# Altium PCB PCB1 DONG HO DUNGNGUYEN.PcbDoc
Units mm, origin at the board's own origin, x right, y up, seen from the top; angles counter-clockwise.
Board outline 54.94 x 47.62 mm, 2 copper layers (Top Layer, Bottom Layer); 32 components, 16 nets, 156 pads, 0 vias.
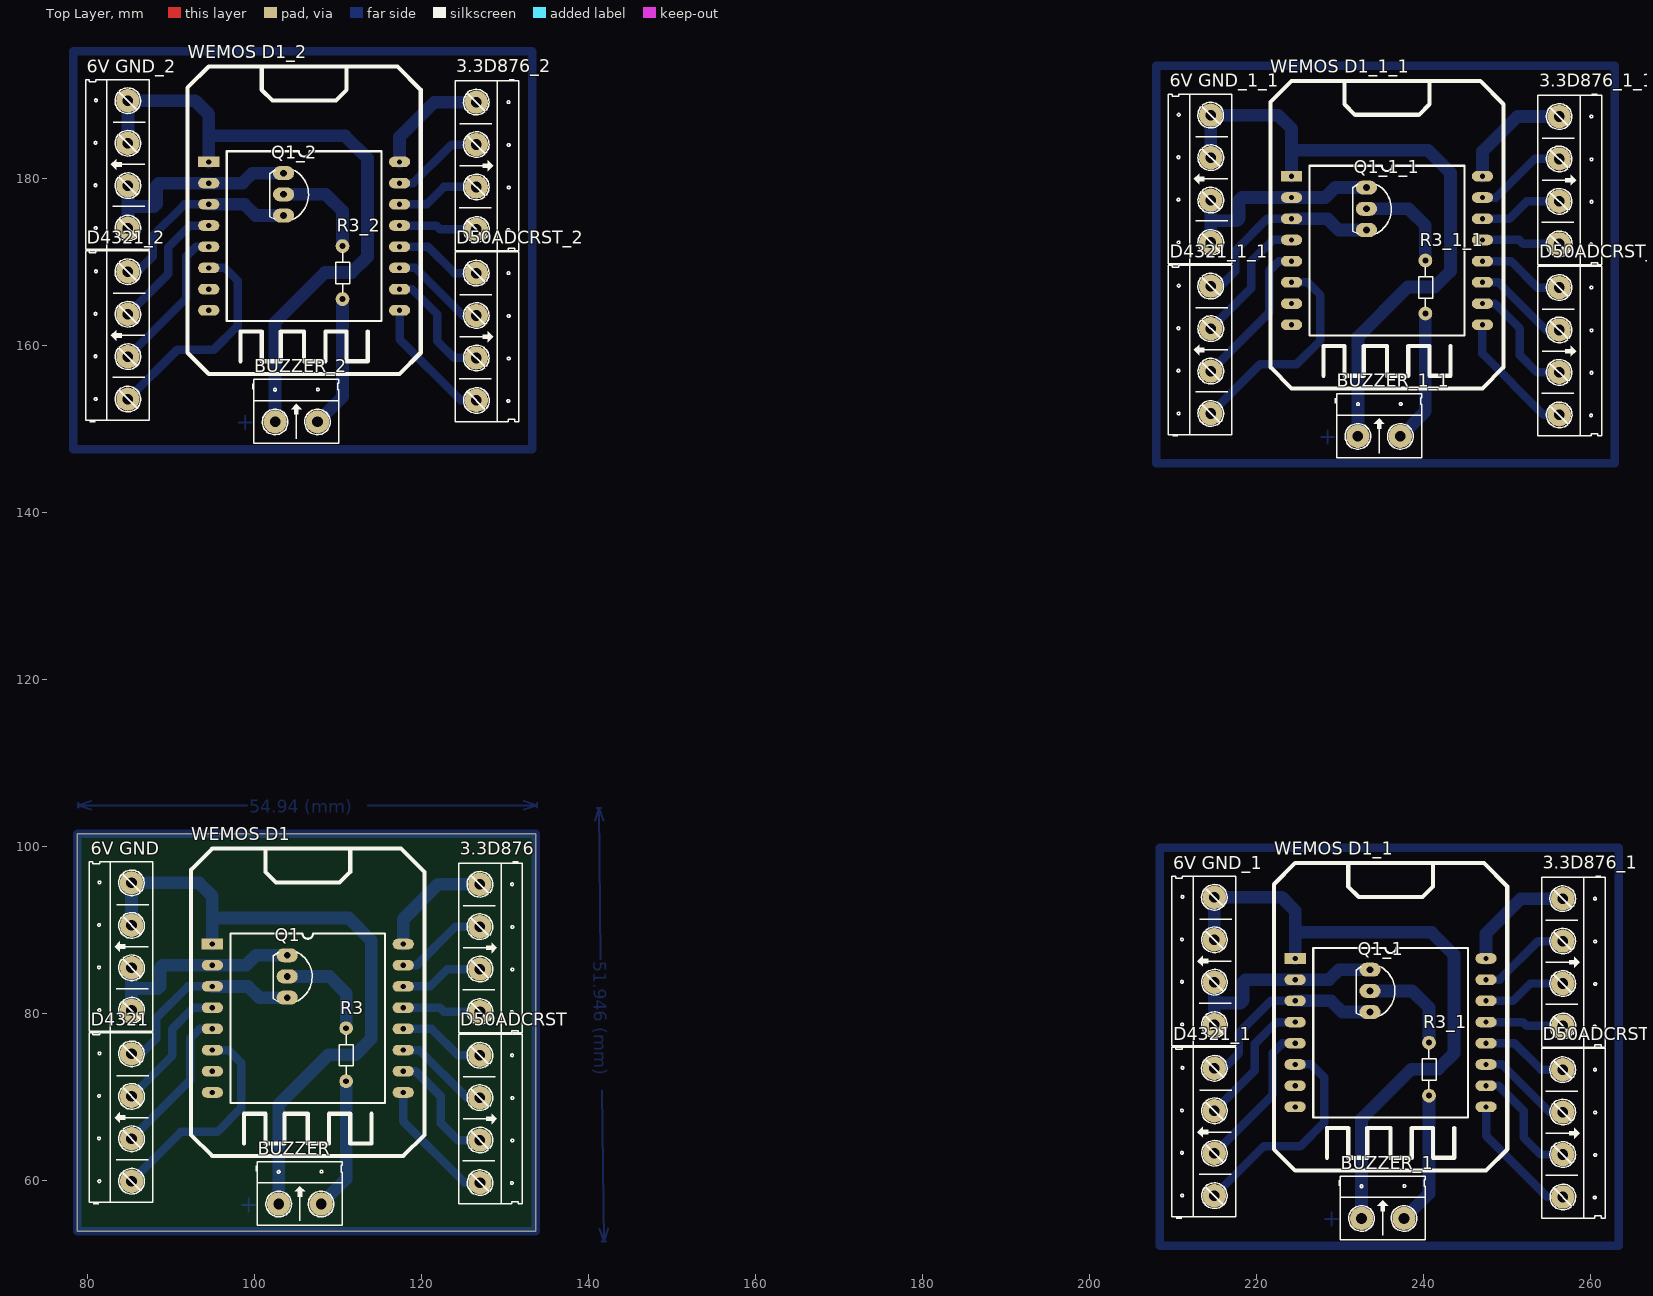
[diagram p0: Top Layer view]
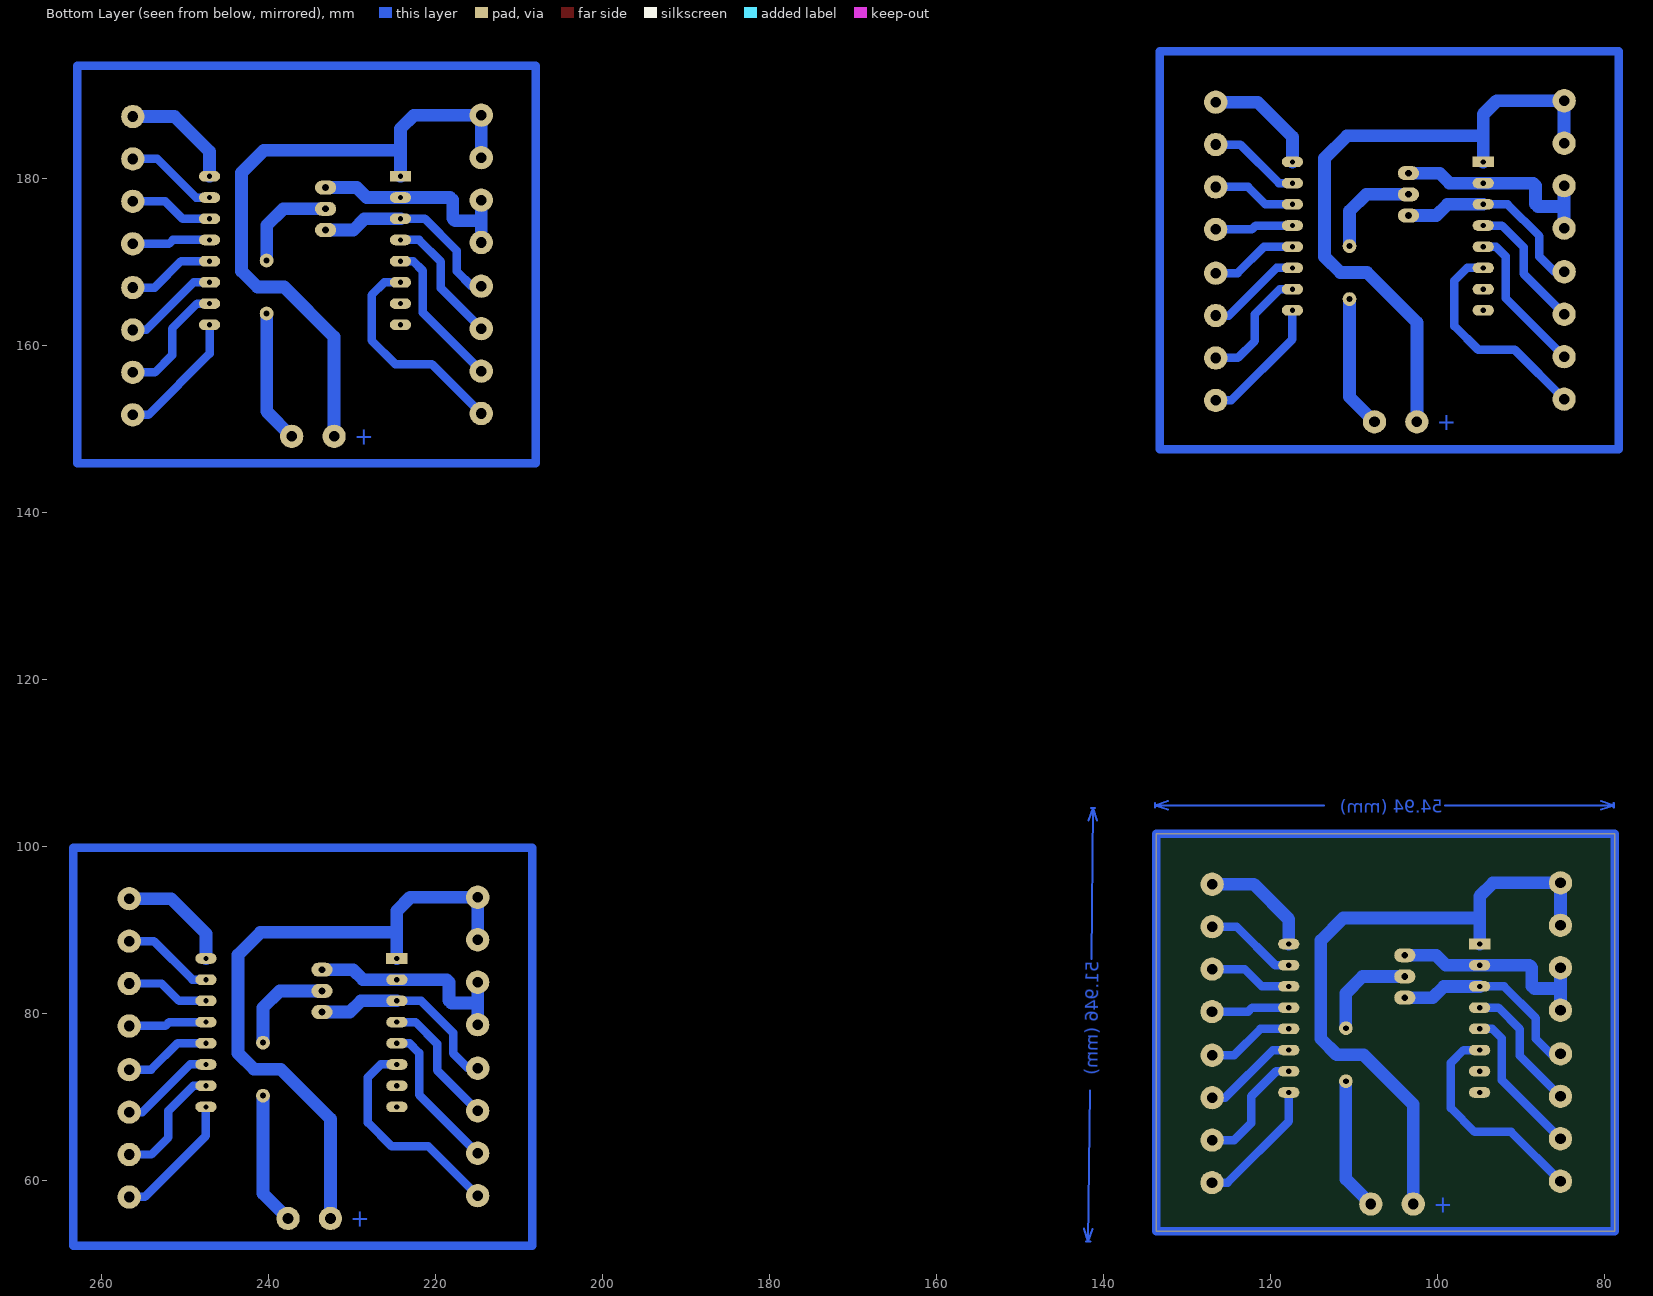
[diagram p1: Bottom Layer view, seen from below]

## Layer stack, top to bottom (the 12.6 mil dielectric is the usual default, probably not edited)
Top Solder: solder mask 0.0102, Solder Resist, Dk 3.5
Top Layer: signal copper 0.0356
Dielectric 1: dielectric 0.32, FR-4, Dk 4.8
Bottom Layer: signal copper 0.0356
Bottom Solder: solder mask 0.0102, Solder Resist, Dk 3.5

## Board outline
78.689,53.975 78.689,101.6 133.629,101.6 133.629,53.975

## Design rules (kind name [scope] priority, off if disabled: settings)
Clearance [All] p1: gap=0.254 ignorepadtopadclearanceinfootprint=FALSE except(0: Arc-Hole Track-Hole SMDPad-Hole THPad-Hole Via-Hole Fill-Hole Poly-Hole Region-Hole Text-Hole)
PolygonConnect [All] p1: connectstyle=Relief reliefconductorwidth=0.254 reliefentries=4 polygonreliefangle="90 Angle" airgapwidth=0.254
RoutingVias [All] p1: holewidth=0.711 width=1.27 viastyle="Through Hole" minholewidth=0.711 minwidth=1.27 maxholewidth=2.54 maxwidth=2.54
SolderMaskExpansion [All] p1: expansion=0.102
Width [All] p1: maxlimit=2.032 minlimit=1.016 preferedwidth=1.524
30 further rules are at their usual default settings.

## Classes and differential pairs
component class DONG_HO: 3.3D876 "6V GND" BUZZER D50ADCRST D4321 HD? Q1 R3 "WEMOS D1"

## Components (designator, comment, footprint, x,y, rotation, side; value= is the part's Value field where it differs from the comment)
3.3D876 "Header 4" HED4 126.939,95.528 r270 top
3.3D876_1 "Header 4" HED4 256.632,93.801 r270 top (schematic designator 3.3D876)
3.3D876_1_1 "Header 4" HED4 256.2,187.476 r270 top (schematic designator 3.3D876)
3.3D876_2 "Header 4" HED4 126.507,189.203 r270 top (schematic designator 3.3D876)
"6V GND" "Header 4" HED4 85.219,80.44 r90 top
"6V GND_1" "Header 4" HED4 214.911,78.713 r90 top (schematic designator "6V GND")
"6V GND_1_1" "Header 4" HED4 214.479,172.388 r90 top (schematic designator "6V GND")
"6V GND_2" "Header 4" HED4 84.787,174.115 r90 top (schematic designator "6V GND")
BUZZER "Header 2" HED2 102.845,57.226 r0 top
BUZZER_1 "Header 2" HED2 232.537,55.499 r0 top (schematic designator BUZZER)
BUZZER_1_1 "Header 2" HED2 232.105,149.174 r0 top (schematic designator BUZZER)
BUZZER_2 "Header 2" HED2 102.413,150.901 r0 top (schematic designator BUZZER)
D50ADCRST "Header 4" HED4 126.939,75.047 r270 top
D50ADCRST_1 "Header 4" HED4 256.632,73.32 r270 top (schematic designator D50ADCRST)
D50ADCRST_1_1 "Header 4" HED4 256.2,166.995 r270 top (schematic designator D50ADCRST)
D50ADCRST_2 "Header 4" HED4 126.507,168.722 r270 top (schematic designator D50ADCRST)
D4321 "Header 4" HED4 85.219,59.959 r90 top
D4321_1 "Header 4" HED4 214.911,58.232 r90 top (schematic designator D4321)
D4321_1_1 "Header 4" HED4 214.479,151.907 r90 top (schematic designator D4321)
D4321_2 "Header 4" HED4 84.787,153.635 r90 top (schematic designator D4321)
Q1 "C1815" QTO-92 103.861,84.48 r270 top
Q1_1 "C1815" QTO-92 233.553,82.753 r270 top (schematic designator Q1)
Q1_1_1 "C1815" QTO-92 233.121,176.428 r270 top (schematic designator Q1)
Q1_2 "C1815" QTO-92 103.429,178.156 r270 top (schematic designator Q1)
R3 "100" RES-1/8W-SMALL 110.922,75.108 r270 top
R3_1 "100" RES-1/8W-SMALL 240.614,73.381 r270 top (schematic designator R3)
R3_1_1 "100" RES-1/8W-SMALL 240.182,167.056 r270 top (schematic designator R3)
R3_2 "100" RES-1/8W-SMALL 110.49,168.783 r270 top (schematic designator R3)
"WEMOS D1" "Component_1" "ESP WEMOS MINI" 94.894,88.367 r0 top
"WEMOS D1_1" "Component_1" "ESP WEMOS MINI" 224.587,86.639 r0 top (schematic designator "WEMOS D1")
"WEMOS D1_1_1" "Component_1" "ESP WEMOS MINI" 224.155,180.315 r0 top (schematic designator "WEMOS D1")
"WEMOS D1_2" "Component_1" "ESP WEMOS MINI" 94.463,182.042 r0 top (schematic designator "WEMOS D1")

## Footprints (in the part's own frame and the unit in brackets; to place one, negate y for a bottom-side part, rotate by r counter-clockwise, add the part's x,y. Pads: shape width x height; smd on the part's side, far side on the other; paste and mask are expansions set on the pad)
"ESP WEMOS MINI" [mm]
  rect 2.54x1.27 hole 0.635: 1(0,0)
  oval 2.54x1.27 hole 0.635: 2(0,-2.54) 3(0,-5.08) 4(0,-7.62) 5(0,-10.16) 6(0,-12.7) 7(0,-15.24) 8(0,-17.78) 9(22.86,-17.78) 10(22.86,-15.24) 11(22.86,-12.7) 12(22.86,-10.16) 13(22.86,-7.62) 14(22.86,-5.08) 15(22.86,-2.54) 16(22.86,0)
  silkscreen extent -2.54,-25.4 25.4,11.43
HED2 [mil] "Header 2, 2 pin, hight 300mil, Pin to Pin 200, Colour Green"
  round 110 hole 50: 1(0,0) 2(200,0)
  silkscreen extent -106,-100 300,200, body extent -92,-140 302,155, height 394
HED4 [mil] "Header 4, 4 pin, hight 300mil, Pin to Pin 200, Colour Green"
  round 110 hole 50: 1(0,0) 2(200,0) 3(400.06,0.06) 4(600.39,0.39)
  silkscreen extent -106,-100 700,200
QTO-92 [mil] "TO-92"
  oval 66x100 hole 32: 1(-100,0) 2(0,0) 3(100,0)
  silkscreen extent -117,-65 120,118, body extent -109,-66 109,95, height 245
RES-1/8W-SMALL [mil] "R 1/8W, 2 pin, 200mil"
  round 65 hole 28: 1(-125,0) 2(125,0)
  silkscreen extent -95,-32 95,34, body extent -135,-35 135,37, height 76

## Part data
3.3D876 3.3D876_1 3.3D876_1_1 3.3D876_2 "6V GND" "6V GND_1" "6V GND_1_1" "6V GND_2" D50ADCRST D50ADCRST_1 D50ADCRST_1_1 D50ADCRST_2 D4321 D4321_1 D4321_1_1 D4321_2: library part Hed4, "Header 4 (Green)"
BUZZER BUZZER_1 BUZZER_1_1 BUZZER_2: library part Hed2, "Header 2 (Green)"
Q1 Q1_1 Q1_1_1 Q1_2: "NPN 600mW, ECB"
R3 R3_1 R3_1_1 R3_2: library part Res, "Res", Manufacturer="Generic Components"

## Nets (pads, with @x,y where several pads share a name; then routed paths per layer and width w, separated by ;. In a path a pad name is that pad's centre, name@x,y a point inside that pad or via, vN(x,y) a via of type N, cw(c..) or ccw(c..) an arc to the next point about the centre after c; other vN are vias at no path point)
D4: "WEMOS D1.3" D4321.4 Q1.3 | length 24
  Bottom Layer w1.016: D4321.4 86.36,75.209 88.163,77.013 88.163,79.477 91.973,83.287 94.894,83.287
  Bottom Layer w1.524: 94.894,83.287 99.187,83.287 100.533,81.94 Q1.3
GND: "6V GND.1" "6V GND.2" "WEMOS D1.2" Q1.1 | length 26.7
  Bottom Layer w1.524: 85.219,80.44 85.219,83.033 ; 85.219,85.52 85.219,83.033 ; Q1.1 100.127,87.02 98.933,85.827 94.894,85.827 88.951,85.827 88.644,85.52 88.644,83.336 88.341,83.033 85.219,83.033
Net3.3D876_1: 3.3D876.1 "WEMOS D1.16" | length 13.9
  Bottom Layer w1.524: 117.754,88.367 117.754,91.338 121.944,95.528 3.3D876.1
Net3.3D876_2: 3.3D876.2 "WEMOS D1.15" | length 11.1
  Bottom Layer w1.016: 117.754,85.827 119.38,85.827 124.001,90.448 3.3D876.2
Net3.3D876_3: 3.3D876.3 "WEMOS D1.14" | length 10
  Bottom Layer w1.016: 117.754,83.287 120.98,83.287 123.06,85.366 3.3D876.3
Net3.3D876_4: 3.3D876.4 "WEMOS D1.13" | length 9.4
  Bottom Layer w1.016: 117.754,80.747 122.149,80.747 122.617,80.278 3.3D876.4
NetBUZZER_2: BUZZER.2 R3.2 | length 15.9
  Bottom Layer w1.524: BUZZER.2 110.922,60.223 R3.2
NetD50ADCRST_1: "WEMOS D1.12" D50ADCRST.1 | length 10.5
  Bottom Layer w1.016: 117.754,78.207 121.158,78.207 124.318,75.047 D50ADCRST.1
NetD50ADCRST_2: "WEMOS D1.11" D50ADCRST.2 | length 11.5
  Bottom Layer w1.016: 117.754,75.667 119.659,75.667 125.359,69.967 D50ADCRST.2
NetD50ADCRST_3: "WEMOS D1.10" D50ADCRST.3 | length 14.5
  Bottom Layer w1.016: 117.754,73.127 119.253,73.127 122.25,70.129 122.25,66.929 124.294,64.885 D50ADCRST.3
NetD50ADCRST_4: "WEMOS D1.9" D50ADCRST.4 | length 15.7
  Bottom Layer w1.016: 117.754,70.587 117.754,67.132 125.09,59.797 D50ADCRST.4
NetD4321_1: "WEMOS D1.6" D4321.1 | length 26.3
  Bottom Layer w1.016: D4321.1 91.121,65.862 95.504,65.862 98.349,68.707 98.349,74.143 96.825,75.667 94.894,75.667
NetD4321_2: "WEMOS D1.5" D4321.2 | length 18.1
  Bottom Layer w1.016: D4321.2 92.227,72.048 92.227,77.064 93.37,78.207 94.894,78.207
NetD4321_3: "WEMOS D1.4" D4321.3 | length 15.9
  Bottom Layer w1.016: D4321.3 90.068,74.972 90.068,78.156 92.659,80.747 94.894,80.747
NetQ1_2: Q1.2 R3.1 | length 12.1
  Bottom Layer w1.524: Q1.2 108.915,84.48 110.922,82.474 R3.1
VCC: "6V GND.3" "6V GND.4" "WEMOS D1.1" BUZZER.1 | length 79.3
  Bottom Layer w1.524: 85.217,90.602 85.217,95.682 85.209,95.69 93.286,95.69 94.894,94.082 94.894,91.491 ; 94.894,88.367 94.894,91.491 ; BUZZER.1 102.845,69.139 108.814,75.108 112.014,75.108 113.919,77.013 113.919,88.798 111.227,91.491 94.894,91.491
pads on no net: 3.3D876_1.1 3.3D876_1.2 3.3D876_1.3 3.3D876_1.4 3.3D876_1_1.1 3.3D876_1_1.2 3.3D876_1_1.3 3.3D876_1_1.4 3.3D876_2.1 3.3D876_2.2 3.3D876_2.3 3.3D876_2.4 "6V GND_1.1" "6V GND_1.2" "6V GND_1.3" "6V GND_1.4" "6V GND_1_1.1" "6V GND_1_1.2" "6V GND_1_1.3" "6V GND_1_1.4" "6V GND_2.1" "6V GND_2.2" "6V GND_2.3" "6V GND_2.4" "WEMOS D1.7" "WEMOS D1.8" "WEMOS D1_1.1" "WEMOS D1_1.2" "WEMOS D1_1.3" "WEMOS D1_1.4" "WEMOS D1_1.5" "WEMOS D1_1.6" "WEMOS D1_1.7" "WEMOS D1_1.8" "WEMOS D1_1.9" "WEMOS D1_1.10" "WEMOS D1_1.11" "WEMOS D1_1.12" "WEMOS D1_1.13" "WEMOS D1_1.14" "WEMOS D1_1.15" "WEMOS D1_1.16" "WEMOS D1_1_1.1" "WEMOS D1_1_1.2" "WEMOS D1_1_1.3" "WEMOS D1_1_1.4" "WEMOS D1_1_1.5" "WEMOS D1_1_1.6" "WEMOS D1_1_1.7" "WEMOS D1_1_1.8" "WEMOS D1_1_1.9" "WEMOS D1_1_1.10" "WEMOS D1_1_1.11" "WEMOS D1_1_1.12" "WEMOS D1_1_1.13" "WEMOS D1_1_1.14" "WEMOS D1_1_1.15" "WEMOS D1_1_1.16" "WEMOS D1_2.1" "WEMOS D1_2.2" "WEMOS D1_2.3" "WEMOS D1_2.4" "WEMOS D1_2.5" "WEMOS D1_2.6" "WEMOS D1_2.7" "WEMOS D1_2.8" "WEMOS D1_2.9" "WEMOS D1_2.10" "WEMOS D1_2.11" "WEMOS D1_2.12" "WEMOS D1_2.13" "WEMOS D1_2.14" "WEMOS D1_2.15" "WEMOS D1_2.16" BUZZER_1.1 BUZZER_1.2 BUZZER_1_1.1 BUZZER_1_1.2 BUZZER_2.1 BUZZER_2.2 D50ADCRST_1.1 D50ADCRST_1.2 D50ADCRST_1.3 D50ADCRST_1.4 D50ADCRST_1_1.1 D50ADCRST_1_1.2 D50ADCRST_1_1.3 D50ADCRST_1_1.4 D50ADCRST_2.1 D50ADCRST_2.2 D50ADCRST_2.3 D50ADCRST_2.4 D4321_1.1 D4321_1.2 D4321_1.3 D4321_1.4 D4321_1_1.1 D4321_1_1.2 D4321_1_1.3 D4321_1_1.4 D4321_2.1 D4321_2.2 D4321_2.3 D4321_2.4 Q1_1.1 Q1_1.2 Q1_1.3 Q1_1_1.1 Q1_1_1.2 Q1_1_1.3 Q1_2.1 Q1_2.2 Q1_2.3 R3_1.1 R3_1.2 R3_1_1.1 R3_1_1.2 R3_2.1 R3_2.2
copper on no net: | length 1856.8
  Bottom Layer w0.254: 78.831,104.724 78.831,105.232 ; 80.355,104.47 78.831,104.978 ; 80.355,105.486 78.831,104.978 ; 99.039,104.978 78.831,104.978 ; 113.563,104.978 133.771,104.978 ; 132.247,104.47 133.771,104.978 ; 132.247,105.486 133.771,104.978 ; 133.771,104.724 133.771,105.232 ; 140.708,103.144 141.199,104.673 ; 140.945,104.671 141.453,104.676 ; 141.258,54.249 141.783,52.73 ; 141.402,86.598 141.199,104.673 ; 141.529,52.728 142.037,52.733 ; 141.58,70.805 141.783,52.73 ; 141.724,103.155 141.199,104.673 ; 142.274,54.26 141.783,52.73
  Bottom Layer w1.016: 84.777,168.885 85.928,168.885 87.732,170.688 87.732,173.152 91.542,176.962 94.463,176.962 ; 84.785,163.796 89.637,168.648 89.637,171.831 92.227,174.422 94.463,174.422 ; 84.787,153.635 90.69,159.537 95.072,159.537 97.917,162.382 97.917,167.818 96.393,169.342 94.463,169.342 ; 84.787,158.715 91.796,165.723 91.796,170.739 92.939,171.882 94.463,171.882 ; 117.323,164.262 117.323,160.807 124.658,153.472 126.517,153.472 ; 117.323,166.802 118.821,166.802 121.818,163.805 121.818,160.604 123.862,158.561 126.509,158.561 ; 117.323,169.342 119.228,169.342 124.927,163.642 126.507,163.642 ; 117.323,171.882 120.726,171.882 123.886,168.722 126.507,168.722 ; 117.323,174.422 121.717,174.422 122.186,173.953 126.517,173.953 ; 117.323,176.962 120.548,176.962 122.628,179.041 126.509,179.041 ; 117.323,179.502 118.948,179.502 123.569,184.123 126.507,184.123 ; 214.469,167.157 215.621,167.157 217.424,168.961 217.424,171.425 221.234,175.235 224.155,175.235 ; 214.478,162.069 219.329,166.92 219.329,170.104 221.92,172.695 224.155,172.695 ; 214.479,151.907 220.382,157.81 224.765,157.81 227.609,160.655 227.609,166.091 226.085,167.615 224.155,167.615 ; 214.479,156.987 221.488,163.996 221.488,169.012 222.631,170.155 224.155,170.155 ; 214.901,73.482 216.052,73.482 217.856,75.286 217.856,77.749 221.666,81.559 224.587,81.559 ; 214.909,68.394 219.761,73.245 219.761,76.429 222.352,79.019 224.587,79.019 ; 214.911,58.232 220.814,64.135 225.196,64.135 228.041,66.98 228.041,72.415 226.517,73.939 224.587,73.939 ; 214.911,63.312 221.92,70.321 221.92,75.336 223.063,76.479 224.587,76.479 ; 247.015,162.535 247.015,159.08 254.35,151.745 256.21,151.745 ; 247.015,165.075 248.514,165.075 251.511,162.077 251.511,158.877 253.554,156.833 256.201,156.833 ; 247.015,167.615 248.92,167.615 254.62,161.915 256.2,161.915 ; 247.015,170.155 250.419,170.155 253.578,166.995 256.2,166.995 ; 247.015,172.695 251.409,172.695 251.878,172.226 256.21,172.226 ; 247.015,175.235 250.241,175.235 252.32,177.314 256.201,177.314 ; 247.015,177.775 248.641,177.775 253.262,182.396 256.2,182.396 ; 247.447,68.859 247.447,65.405 254.782,58.07 256.642,58.07 ; 247.447,71.399 248.945,71.399 251.943,68.402 251.943,65.202 253.986,63.158 256.633,63.158 ; 247.447,73.939 249.352,73.939 255.051,68.24 256.632,68.24 ; 247.447,76.479 250.85,76.479 254.01,73.32 256.632,73.32 ; 247.447,79.019 251.841,79.019 252.31,78.551 256.642,78.551 ; 247.447,81.559 250.673,81.559 252.752,83.639 256.633,83.639 ; 247.447,84.099 249.072,84.099 253.694,88.721 256.632,88.721 ; 78.257,147.65 133.198,147.65 133.198,195.275 78.257,195.275 78.257,147.65 ; 78.689,53.975 78.689,101.6 133.629,101.6 133.629,53.975 78.689,53.975 ; 207.95,145.923 207.95,193.548 262.89,193.548 262.89,145.923 207.95,145.923 ; 208.382,52.248 263.322,52.248 263.322,99.873 208.382,99.873 208.382,52.248
  Bottom Layer w1.524: 84.785,184.277 84.785,189.357 84.777,189.365 92.854,189.365 94.463,187.757 94.463,185.166 ; 84.787,174.115 84.787,176.708 ; 84.787,179.195 84.787,176.708 ; 94.463,176.962 98.755,176.962 100.101,175.616 103.429,175.616 ; 94.463,182.042 94.463,185.166 ; 102.413,150.901 102.413,162.814 108.382,168.783 111.582,168.783 113.487,170.688 113.487,182.474 110.795,185.166 94.463,185.166 ; 103.429,178.156 108.483,178.156 110.49,176.149 110.49,171.958 ; 103.429,180.696 99.695,180.696 98.501,179.502 94.463,179.502 88.519,179.502 88.213,179.195 88.213,177.011 87.909,176.708 84.787,176.708 ; 107.493,150.901 110.49,153.899 110.49,165.608 ; 117.323,182.042 117.323,185.014 121.512,189.203 126.507,189.203 ; 214.478,182.55 214.478,187.63 214.469,187.638 222.546,187.638 224.155,186.03 224.155,183.439 ; 214.479,172.388 214.479,174.981 ; 214.479,177.468 214.479,174.981 ; 214.909,88.875 214.909,93.955 214.901,93.963 222.978,93.963 224.587,92.354 224.587,89.764 ; 214.911,78.713 214.911,81.305 ; 214.911,83.793 214.911,81.305 ; 224.155,175.235 228.448,175.235 229.794,173.888 233.121,173.888 ; 224.155,180.315 224.155,183.439 ; 224.587,81.559 228.879,81.559 230.226,80.213 233.553,80.213 ; 224.587,86.639 224.587,89.764 ; 232.105,149.174 232.105,161.087 238.074,167.056 241.275,167.056 243.18,168.961 243.18,180.746 240.487,183.439 224.155,183.439 ; 232.537,55.499 232.537,67.412 238.506,73.381 241.706,73.381 243.611,75.286 243.611,87.071 240.919,89.764 224.587,89.764 ; 233.121,176.428 238.176,176.428 240.182,174.422 240.182,170.231 ; 233.121,178.968 229.387,178.968 228.194,177.775 224.155,177.775 218.211,177.775 217.905,177.468 217.905,175.284 217.602,174.981 214.479,174.981 ; 233.553,82.753 238.608,82.753 240.614,80.747 240.614,76.556 ; 233.553,85.293 229.819,85.293 228.625,84.099 224.587,84.099 218.643,84.099 218.337,83.793 218.337,81.609 218.034,81.305 214.911,81.305 ; 237.185,149.174 240.182,152.171 240.182,163.881 ; 237.617,55.499 240.614,58.496 240.614,70.206 ; 247.015,180.315 247.015,183.286 251.204,187.476 256.2,187.476 ; 247.447,86.639 247.447,89.611 251.636,93.801 256.632,93.801

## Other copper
Bottom Layer:
  text "+" at 97.688,149.885 h2
  text "+" at 227.381,148.158 h2
  text "54.94 (mm)" at 99.293,104.064 h1.52
  text "51.946 (mm)" at 140.491,86.334 h1.52 r270.64
  text "+" at 98.12,56.21 h2
  text "+" at 227.813,54.483 h2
